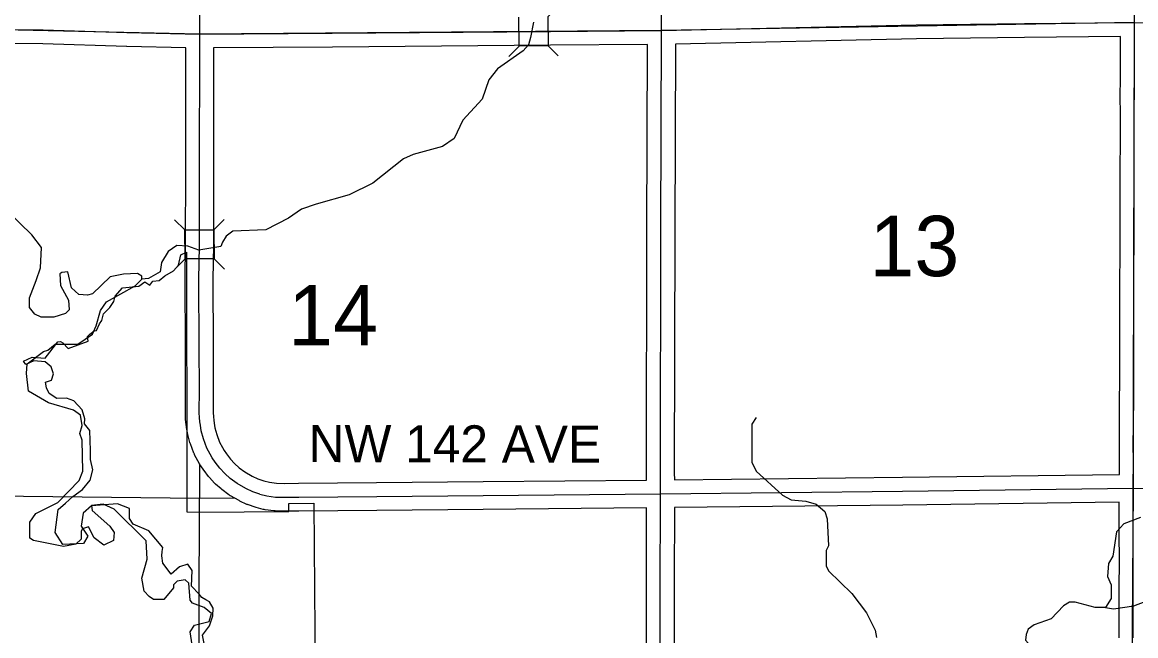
# Model space of a CAD drawing. Extents: x -1403959 to 81668, y -1400582 to 11018.
# Drawn here: x 6572.9 to 6804.9, y 9769.7 to 9897.5 of the extents above; entities that cross this region are included whole.
import ezdxf

# ---------------------------------------------------------------- set-up
doc = ezdxf.new("R2010")
doc.units = 0
for name, color, linetype in [('tdCiCoBndryTxt', 7, 'Continuous'), ('tdCiMapFrame', 7, 'Continuous'), ('tdCiRRCL', 7, 'Continuous'), ('tdCiSecText', 7, 'Continuous'), ('tdCiSectLine', 7, 'Continuous'), ('tdCoCityStreetMajor', 7, 'Continuous'), ('tdCoClipBndry', 7, 'Continuous'), ('tdCoSectLinePart', 7, 'Continuous'), ('tdCoSectNmbr', 7, 'Continuous'), ('tdCoSurfBitum', 7, 'Continuous')]:
    doc.layers.add(name, color=color, linetype=linetype)

msp = doc.modelspace()

# ---------------------------------------------------------------- linework, layer by layer
at = {"layer": 'tdCiCoBndryTxt'}
for points in [[(6804.36, 9769.25), (6804.34, 9776.67), (6804.35, 9780.53), (6804.39, 9784.32), (6804.38, 9792.06), (6804.36, 9798.91), (6804.37, 9800.46), (6804.41, 9806.38), (6804.38, 9809.28), (6804.41, 9813.71), (6804.41, 9818.13), (6804.45, 9823.24), (6804.45, 9829.17), (6804.49, 9835.79), (6804.48, 9842.51), (6804.52, 9849.89), (6804.53, 9856.93), (6804.55, 9860.91), (6804.55, 9864.57), (6804.57, 9872.09), (6804.59, 9878.82), (6804.57, 9881.73), (6804.62, 9886.19), (6804.61, 9889.87), (6804.65, 9893.63), (6804.64, 9897.53), (6804.63, 9901.19)], [(6609.75, 9829.95), (6609.68, 9843.97), (6609.8, 9850.97)], [(6622.35, 9799.23), (6620.9, 9799.72), (6619.45, 9800.4), (6617.63, 9801.42), (6616.21, 9802.49), (6615.05, 9803.51), (6614, 9804.65), (6613.05, 9805.91), (6612.43, 9806.79), (6612, 9807.58), (6611.33, 9808.81), (6610.61, 9810.74), (6610.15, 9812.43), (6609.97, 9813.57), (6609.86, 9814.28), (6609.79, 9815.18), (6609.75, 9816.19), (6609.77, 9821.02), (6609.75, 9829.95)], [(6705.88, 9799.28), (6705.83, 9803.64)], [(6622.35, 9799.23), (6623.83, 9798.84), (6625.63, 9798.62), (6627.46, 9798.56), (6630.46, 9798.59), (6646.73, 9798.75), (6668.9, 9798.94), (6705.88, 9799.28), (6756.32, 9799.86), (6804.36, 9800.46)], [(6706.2, 9654.39), (6705.79, 9703.38), (6705.84, 9750.93), (6705.82, 9781.7), (6705.86, 9796.01), (6705.88, 9799.28)], [(6804.36, 9800.46), (6804.37, 9800.46)], [(6804.37, 9800.46), (6820.92, 9800.23), (6865.81, 9799.68), (6900.93, 9799.29), (6929.31, 9799.17), (6956.04, 9799.06), (6998.31, 9799.1), (6998.34, 9799.1), (7085.1, 9797.77), (7096.29, 9797.58), (7096.33, 9797.58)]]:
    msp.add_lwpolyline(points, dxfattribs=at)
at = {"layer": 'tdCiMapFrame'}
for points in [[(6705.83, 9803.64), (6705.93, 9854.06), (6706.07, 9895.84), (6706.1, 9903.07), (6706.32, 9934.74), (6706.29, 9941.72), (6706.43, 9956.1), (6706.77, 9992.71), (6706.67, 9998.63), (6706.34, 10021.5), (6706.01, 10049.56), (6705.93, 10061.79), (6705.75, 10070.51), (6705.56, 10085.58)], [(6609.84, 9895.08), (6609.67, 9926.38), (6609.48, 9954.95), (6609.06, 9991.95)], [(6534.34, 9897.49), (6535.94, 9897.07), (6537.17, 9896.9), (6538.74, 9896.7), (6541.61, 9896.57), (6555.09, 9896.38), (6564.18, 9896.13), (6577.2, 9895.94), (6594.68, 9895.41), (6609.84, 9895.08)], [(6609.84, 9895.08), (6609.84, 9895.08), (6637.47, 9895.29), (6682.91, 9895.65), (6706.07, 9895.84), (6759.14, 9896.98), (6781.69, 9897.27), (6804.59, 9897.53)], [(6804.59, 9897.53), (6804.64, 9897.53), (6828.75, 9897.24), (6865.94, 9896.8), (6902.12, 9896.4), (6957.68, 9896.48), (6968.43, 9896.4), (6975.47, 9896.35), (6999.19, 9896.06), (6999.21, 9896.06), (7040.75, 9895.55), (7085.11, 9894.91), (7097.42, 9894.66), (7097.46, 9894.66), (7166.82, 9894.22), (7193.47, 9893.93)], [(6609.8, 9850.97), (6609.81, 9851.17), (6609.79, 9853.79), (6609.81, 9864.39), (6609.84, 9895.08)]]:
    msp.add_lwpolyline(points, dxfattribs=at)
at = {"layer": 'tdCiRRCL'}
msp.add_lwpolyline([(6610.75, 9768.09), (6610.45, 9769.83), (6611.89, 9771.79), (6612.56, 9773.9), (6612.64, 9775.48), (6611.89, 9776.77), (6611.09, 9777.22), (6610.3, 9777.67), (6609.75, 9778.35), (6608.1, 9780.03), (6608.29, 9783.31), (6607.33, 9784.66), (6605.59, 9784.09), (6603.86, 9782.54), (6602.12, 9784.86), (6601.93, 9786.4), (6602.02, 9787.27), (6602.12, 9788.14), (6599.23, 9791.61), (6595.95, 9792.96), (6595.18, 9794.12), (6595.18, 9796.24), (6592.67, 9797.2), (6587.27, 9796.82), (6585.53, 9795.27), (6585.15, 9792.57), (6586.5, 9790.45), (6585.6, 9788.91), (6581.29, 9788.72), (6579.74, 9791.22), (6580.32, 9796.05), (6581.87, 9797.37), (6583.41, 9798.7), (6585.4, 9800.21), (6587.04, 9802.14), (6587.56, 9804.29), (6587.11, 9806.45), (6587.11, 9808.31), (6586.96, 9812.47), (6585.83, 9813.9), (6585.92, 9814.92), (6585.33, 9816.78), (6583.62, 9818.64), (6582.06, 9819.23), (6580.05, 9819.16), (6578.49, 9820.2), (6577.9, 9821.38), (6577.67, 9822.57), (6578.94, 9822.95), (6579.38, 9824.28), (6578.86, 9825.77), (6577.6, 9826.81), (6575.29, 9827.03), (6573.59, 9826.21), (6573.14, 9826.96), (6574.92, 9827.78), (6577.6, 9827.55), (6580.27, 9830.97), (6580.79, 9831.04), (6581.31, 9830.75), (6582.43, 9829.56), (6586.59, 9831.12), (6586.44, 9832.08), (6586.96, 9832.53), (6587.85, 9833.27), (6588.3, 9833.35), (6588.97, 9834.69), (6589.41, 9835.43), (6589.78, 9836.77), (6591.12, 9838.1), (6591.94, 9839.37), (6592.24, 9840.48), (6593.72, 9842.2), (6597.14, 9842.56), (6598.39, 9843.46), (6599.45, 9842.77), (6600.04, 9843.6), (6601.37, 9843.76), (6602.57, 9844.72), (6604.39, 9845.75), (6605.39, 9846.95), (6605.91, 9849.09), (6607.1, 9849.62), (6607.1, 9847.94), (6607.15, 9803.71), (6607.15, 9798.44), (6607.14, 9795.51), (6609.8, 9795.47), (6628.39, 9795.64), (6628.4, 9797.29), (6633.62, 9797.34), (6633.95, 9752.87)], dxfattribs=at)
at = {"layer": 'tdCiSecText'}
for points in [[(6684.5, 9900.83), (6682.38, 9898.67), (6682.43, 9892.62)], [(6674.25, 9890.42), (6676.38, 9892.57), (6676.33, 9898.63)], [(6684.54, 9890.55), (6682.43, 9892.62), (6676.38, 9892.57)], [(6604.58, 9856.4), (6606.73, 9854.27), (6612.78, 9854.31)], [(6614.91, 9856.46), (6612.78, 9854.31), (6612.82, 9848.25)], [(6604.68, 9846.11), (6606.77, 9848.22), (6606.73, 9854.27)], [(6614.97, 9846.13), (6612.82, 9848.25), (6606.77, 9848.22)]]:
    msp.add_lwpolyline(points, dxfattribs=at)
at = {"layer": 'tdCiSectLine'}
for points in [[(6708.75, 9802.21), (6756.29, 9802.76), (6801.49, 9803.33), (6801.51, 9806.38), (6801.48, 9809.25), (6801.48, 9809.28), (6801.48, 9809.31), (6801.51, 9813.72), (6801.51, 9818.13), (6801.51, 9818.13), (6801.51, 9818.15), (6801.55, 9823.25), (6801.55, 9829.17), (6801.55, 9829.19), (6801.59, 9835.79), (6801.58, 9842.51), (6801.58, 9842.51), (6801.58, 9842.53), (6801.62, 9849.9), (6801.62, 9856.93), (6801.62, 9856.94), (6801.64, 9860.92), (6801.69, 9878.81), (6801.67, 9881.72), (6801.67, 9881.73), (6801.67, 9881.76), (6801.71, 9886.2), (6801.71, 9889.87), (6801.71, 9889.87), (6801.71, 9889.9), (6801.74, 9893.64), (6801.74, 9894.59), (6781.72, 9894.36), (6759.19, 9894.08), (6709, 9893), (6709, 9892.96), (6708.97, 9892.96), (6708.83, 9854.05), (6708.74, 9803.66), (6708.75, 9802.21)], [(6702.93, 9753.82), (6702.92, 9781.7), (6702.92, 9781.7), (6702.92, 9781.71), (6702.96, 9796.01), (6702.96, 9796.02), (6702.96, 9796.35), (6668.92, 9796.04), (6668.92, 9796.04), (6646.76, 9795.84), (6630.49, 9795.69), (6630.48, 9795.69), (6627.48, 9795.66), (6627.46, 9795.66), (6627.36, 9795.66), (6625.54, 9795.72), (6625.44, 9795.73), (6625.28, 9795.74), (6623.48, 9795.96), (6623.45, 9795.97), (6623.26, 9796), (6623.09, 9796.04), (6621.61, 9796.42), (6621.59, 9796.43), (6621.42, 9796.48), (6619.97, 9796.97), (6619.96, 9796.97), (6619.79, 9797.04), (6619.66, 9797.09), (6618.21, 9797.77), (6618.16, 9797.8), (6618.03, 9797.87), (6616.22, 9798.88), (6616.18, 9798.9), (6616.02, 9799), (6615.88, 9799.1), (6614.46, 9800.18), (6614.45, 9800.19), (6614.3, 9800.31), (6613.14, 9801.33), (6613.14, 9801.33), (6613, 9801.46), (6612.92, 9801.54), (6611.87, 9802.69), (6611.82, 9802.74), (6611.7, 9802.88), (6611.69, 9802.9), (6610.73, 9804.16), (6610.68, 9804.24), (6610.06, 9805.11), (6610.02, 9805.17), (6609.92, 9805.34), (6609.88, 9805.4), (6609.45, 9806.19), (6609.45, 9806.19), (6608.78, 9807.43), (6608.73, 9807.53), (6608.65, 9807.7), (6608.61, 9807.79), (6607.89, 9809.73), (6607.86, 9809.81), (6607.8, 9809.99), (6607.35, 9811.68), (6607.35, 9811.68), (6607.31, 9811.86), (6607.29, 9811.97), (6607.11, 9813.12), (6607.1, 9813.13), (6606.99, 9813.84), (6606.99, 9813.9), (6606.97, 9814.05), (6606.9, 9814.95), (6606.89, 9814.99), (6606.89, 9815.08), (6606.85, 9816.09), (6606.85, 9816.19), (6606.85, 9816.21), (6606.87, 9821.02), (6606.85, 9829.94), (6606.78, 9843.95), (6606.78, 9843.97), (6606.78, 9844.02), (6606.9, 9851.19), (6606.89, 9853.77), (6606.89, 9853.79), (6606.89, 9853.79), (6606.91, 9864.4), (6606.94, 9892.24), (6594.62, 9892.5), (6594.59, 9892.5), (6577.13, 9893.04), (6564.14, 9893.22)], [(6627.49, 9801.47), (6630.43, 9801.49), (6646.7, 9801.65), (6646.7, 9801.65), (6668.87, 9801.84), (6702.95, 9802.15), (6702.93, 9803.61), (6702.93, 9803.64), (6702.93, 9803.65), (6703.03, 9854.06), (6703.03, 9854.07), (6703.16, 9892.91), (6682.93, 9892.75), (6682.93, 9892.75), (6637.49, 9892.39), (6637.49, 9892.39), (6612.76, 9892.2), (6612.76, 9892.2), (6612.74, 9892.2), (6612.72, 9864.39), (6612.72, 9864.39), (6612.69, 9853.79), (6612.71, 9851.19), (6612.71, 9851.17), (6612.71, 9851.12), (6612.58, 9843.95), (6612.66, 9829.96), (6612.66, 9829.95), (6612.67, 9821.02), (6612.67, 9821.02), (6612.67, 9821), (6612.66, 9816.24), (6612.69, 9815.35), (6612.75, 9814.61), (6612.84, 9814.02), (6612.99, 9813.03), (6613.37, 9811.63), (6613.98, 9810.02), (6614.55, 9808.97), (6614.9, 9808.32), (6615.39, 9807.63), (6616.23, 9806.51), (6617.08, 9805.59), (6618.05, 9804.74), (6619.23, 9803.85), (6620.77, 9802.98), (6621.98, 9802.42), (6623.18, 9802.01), (6624.37, 9801.7), (6625.86, 9801.52), (6627.49, 9801.47)], [(6801.46, 9769.25), (6801.44, 9776.67), (6801.44, 9776.67), (6801.44, 9776.68), (6801.45, 9780.53), (6801.45, 9780.56), (6801.49, 9784.33), (6801.47, 9792.05), (6801.46, 9797.52), (6756.36, 9796.96), (6756.36, 9796.96), (6708.81, 9796.41), (6708.81, 9796.41), (6708.81, 9796.41), (6708.81, 9796.4), (6708.77, 9796.4), (6708.76, 9795.99), (6708.72, 9781.7), (6708.74, 9753.83)]]:
    msp.add_lwpolyline(points, dxfattribs=at)
at = {"layer": 'tdCoCityStreetMajor'}
for points in [[(6609.78, 9805.57), (6609.78, 9798.41)], [(6511.83, 9799.49), (6609.78, 9798.41)], [(6609.5, 9701.61), (6609.78, 9798.41)], [(6609.78, 9798.41), (6616.99, 9798.48)]]:
    msp.add_lwpolyline(points, dxfattribs=at)
at = {"layer": 'tdCoClipBndry'}
for points in [[(6803.02, 10046.01), (6803.28, 9994.33), (6804.56, 9897.53), (6804.33, 9800.46), (6803.65, 9703.3)], [(6804.56, 9897.53), (6706.04, 9895.84), (6609.81, 9895.08), (6512.06, 9897.22), (6415.88, 9896.14), (6416.14, 9799.39), (6416.13, 9703.49), (6416.74, 9653.75)]]:
    msp.add_lwpolyline(points, dxfattribs=at)
at = {"layer": 'tdCoSurfBitum'}
for points in [[(6679.4, 9897.56), (6678.79, 9894.35), (6678.33, 9892.83), (6677.25, 9891.61), (6671.9, 9887.81), (6670.06, 9885.52), (6668.68, 9881.55), (6664.7, 9877.14), (6662.86, 9873.32), (6660.42, 9871.65), (6654.31, 9869.98), (6652.32, 9869.07), (6645.9, 9864.05), (6641, 9861.62), (6634.13, 9859.65), (6631.07, 9858.59), (6628.32, 9856.76), (6623.58, 9854.33), (6616.71, 9854.04), (6615.33, 9852.98), (6614.57, 9851.76), (6614.26, 9850.84), (6609.68, 9850.09), (6607.39, 9850.86), (6605.1, 9851.02), (6603.27, 9849.8), (6601.89, 9847.51), (6601.58, 9845.53), (6599.13, 9844.16), (6597.76, 9844.01)], [(6608.29, 9767.81), (6607.83, 9770.56), (6608.75, 9771.93), (6611.81, 9772.69), (6612.27, 9774.37), (6610.75, 9775.59), (6608.3, 9776.51), (6607.85, 9777.13), (6607.55, 9780.64), (6606.79, 9781.4), (6605.11, 9781.1), (6604.34, 9780.34), (6604.34, 9779.73), (6602.35, 9777.29), (6600.21, 9777.3), (6599.3, 9777.91), (6598.23, 9778.98), (6597.78, 9781.73), (6598.86, 9785.69), (6598.71, 9789.51), (6592.01, 9796.09), (6589.72, 9797.16), (6587.28, 9796.87), (6587.43, 9795.8), (6591.08, 9792.58), (6592, 9791.21), (6591.84, 9789.53), (6589.85, 9788.62), (6587.87, 9790.15), (6586.66, 9792.44), (6585.43, 9791.98), (6585.13, 9791.53), (6585.12, 9789.85), (6584.05, 9788.78), (6581.46, 9788.33), (6575.2, 9789.57), (6574.44, 9790.03), (6574.44, 9793.38), (6575.67, 9795.21), (6580.25, 9797.49), (6584.69, 9802.06), (6585.46, 9804.04), (6585.32, 9810.46), (6584.86, 9811.83), (6585.33, 9813.51), (6585.02, 9815.65), (6583.5, 9816.72), (6578.31, 9818.26), (6574.19, 9820.71), (6573.74, 9824.37), (6573.9, 9826.36), (6577.27, 9828.94), (6578.18, 9829.25), (6579.71, 9830.47), (6584.44, 9830.46), (6587.5, 9832.59), (6588.27, 9834.26), (6589.19, 9837.47), (6590.42, 9839.3), (6596.38, 9842.64), (6597.76, 9844.01), (6597.76, 9844.62), (6596.84, 9845.23), (6593.94, 9845.09), (6591.19, 9844.48), (6587.52, 9840.98), (6586.45, 9840.68), (6584.62, 9840.83), (6583.09, 9842.21), (6582.34, 9845.57), (6581.12, 9845.42), (6580.66, 9845.12), (6580.81, 9842.68), (6582.48, 9839.62), (6582.63, 9837.63), (6581.86, 9836.87), (6579.42, 9836.11), (6576.82, 9836.12), (6575.45, 9836.73), (6574.38, 9838.11), (6574.39, 9840.1), (6575.77, 9843.76), (6576.69, 9846.35), (6576.85, 9850.62), (6574.87, 9853.22), (6567.41, 9860.41)], [(6725.8, 9815.17), (6724.89, 9813.8), (6724.87, 9805.86), (6725.78, 9804.03), (6731.27, 9798.98), (6733.1, 9798.06), (6736.15, 9797.75), (6738.29, 9797.13), (6740.12, 9795.6), (6740.57, 9794.07), (6740.87, 9788.42), (6740.41, 9787.51), (6740.4, 9784.3), (6740.85, 9783.23), (6745.73, 9778.49), (6748.78, 9774.52), (6750.6, 9770.85), (6750.9, 9769.32)], [(6805.92, 9794.38), (6802.41, 9793.02), (6800.88, 9791.34), (6800.11, 9786.31), (6799.19, 9784.78), (6799.03, 9782.03), (6799.79, 9780.35), (6799.78, 9777.45), (6798.56, 9775.62), (6800.24, 9775.32), (6804.51, 9775.92), (6809.25, 9777.74)], [(6798.56, 9775.62), (6796.42, 9775.63), (6792.3, 9776.71), (6791.08, 9776.71), (6789.85, 9775.95), (6787.25, 9773.21), (6783.74, 9771.99), (6782.51, 9771.08), (6782.05, 9770.01), (6781.9, 9768.79), (6782.51, 9768.18), (6782.51, 9767.57), (6784.34, 9765.89), (6784.79, 9764.66), (6784.94, 9761.61), (6785.7, 9761), (6786.16, 9760.39)]]:
    msp.add_lwpolyline(points, dxfattribs=at)

# ---------------------------------------------------------------- texts
at = {"layer": 'tdCoSectLinePart'}
for s, rotation, p in [('13', 359.9921, (6749.41, 9844.64)), ('14', 359.9912, (6628.27, 9830.2))]:
    msp.add_text(s, height=12.575, rotation=rotation, dxfattribs=at).set_placement(p)
at = {"layer": 'tdCoSectNmbr'}
msp.add_text('NW 142 AVE', height=7.738, rotation=359.8722, dxfattribs=at).set_placement((6632.52, 9805.9))

doc.saveas('drawing.dxf')
